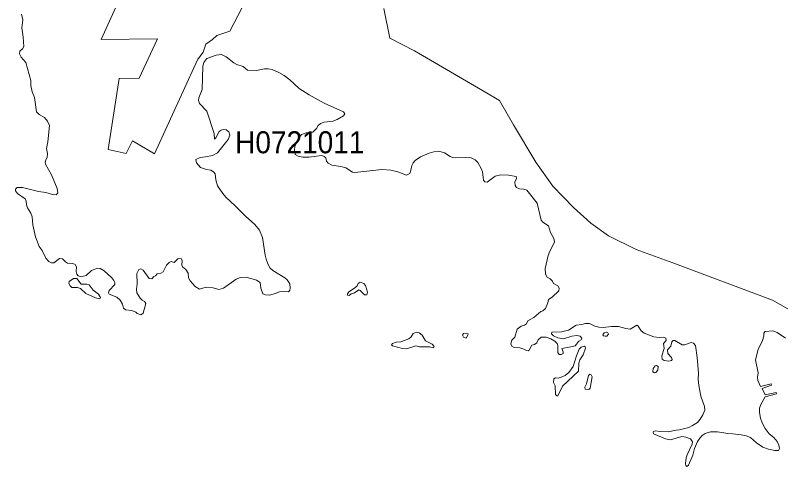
# Model space of a CAD drawing. Extents: x 369010 to 739155, y 6377141 to 6616555.
# Drawn here: x 385920 to 389405, y 6449209 to 6451258 of the extents above; entities that cross this region are included whole.
import ezdxf
from ezdxf.enums import TextEntityAlignment as Align

# ---------------------------------------------------------------- set-up
doc = ezdxf.new("R2010")
doc.units = 0
doc.header["$LTSCALE"] = 40
doc.layers.add('1', color=7, linetype='Continuous', lineweight=13)
doc.layers.add('2', color=7, linetype='Continuous')

msp = doc.modelspace()

# ---------------------------------------------------------------- linework, layer by layer
at = {"layer": '1'}
for points in [[(386471.87, 6451509.71), (386308.85, 6451148.91), (386564.22, 6451151.07), (386481.14, 6450972.32), (386390.94, 6450971.66), (386341.12, 6450648.93), (386421.56, 6450630.22), (386451.68, 6450687.82), (386550.65, 6450628.9), (386745.78, 6451055.74), (386747.27, 6451058.88), (386749.92, 6451061.86), (386772.26, 6451090.16), (386783.02, 6451126.9), (386813.31, 6451148.58), (386832.84, 6451165.8), (386891.92, 6451185.82), (387036.07, 6451462.54)], [(387036.07, 6451462.54), (386891.92, 6451185.82), (386832.84, 6451165.8), (386813.31, 6451148.58), (386783.02, 6451126.9), (386772.26, 6451090.16), (386749.92, 6451061.86), (386747.27, 6451058.88), (386745.78, 6451055.74), (386550.65, 6450628.9), (386451.68, 6450687.82), (386421.56, 6450630.22), (386341.12, 6450648.93), (386390.94, 6450971.66), (386481.14, 6450972.32), (386564.22, 6451151.07), (386308.85, 6451148.91), (386471.87, 6451509.71)], [(385948.05, 6451262.62), (385954.01, 6451237.96), (385948.88, 6451200.55), (385955.33, 6451158.68), (385958.64, 6451116.14), (385951.53, 6451106.05), (385939.28, 6451094.96), (385938.29, 6451083.21), (385946.07, 6451067.49), (385966.59, 6451044.32), (385989.92, 6450961.89), (385990.25, 6450939.72), (385995.05, 6450910.59), (386005.65, 6450885.27), (386014.75, 6450820.06), (386027.16, 6450808.47), (386051.99, 6450793.91), (386065.56, 6450777.03), (386073.83, 6450757.99), (386066.22, 6450684.34), (386060.1, 6450653.73), (386065.39, 6450631.55), (386064.57, 6450612.85), (386057.95, 6450601.59), (386055.46, 6450591.33), (386055.79, 6450581.73), (386083.27, 6450534.73), (386109.09, 6450472.66), (386112.89, 6450451.98), (386104.78, 6450443.21), (386088.4, 6450444.36), (386058.28, 6450454.46), (386024.18, 6450458.27), (385952.02, 6450476.47), (385928.36, 6450475.81), (385920.08, 6450469.35), (385919.58, 6450461.74), (385929.02, 6450449), (385964.27, 6450425.33), (385968.24, 6450414.41), (385969.73, 6450398.52), (385974.04, 6450383.62), (385989.59, 6450359.96), (385995.72, 6450342.74), (385999.36, 6450307.16), (386011.6, 6450252.88), (386027.66, 6450209.18), (386040.73, 6450190.31), (386057.61, 6450155.39), (386070.86, 6450140.5), (386083.1, 6450134.54)], [(387591.67, 6451288.6), (387617.99, 6451153.71), (387730.36, 6451097.28), (388021.15, 6450927.64), (388116.15, 6450871.86), (388179.54, 6450760.31), (388280.17, 6450591.66), (388357.79, 6450482.93), (388451.63, 6450385.11), (388529.58, 6450314.44), (388610.18, 6450257.34), (388735.8, 6450195.45), (388901.97, 6450134.87), (389354.12, 6449965.06), (389424.3, 6449925.67)], [(389424.3, 6449925.67), (389354.12, 6449965.06), (388901.97, 6450134.87), (388735.8, 6450195.45), (388610.18, 6450257.34), (388529.58, 6450314.44), (388451.63, 6450385.11), (388357.79, 6450482.93), (388280.17, 6450591.66), (388179.54, 6450760.31), (388116.15, 6450871.86), (388021.15, 6450927.64), (387730.36, 6451097.28), (387617.99, 6451153.71), (387591.67, 6451288.6)], [(387005.79, 6450308.65), (386963.09, 6450346.55), (386917.41, 6450393.88), (386875.04, 6450432.28), (386860.97, 6450448.67), (386836.64, 6450484.75), (386829.03, 6450510.73), (386825.55, 6450539.03), (386818.77, 6450548.3), (386806.52, 6450554.42), (386786.33, 6450557.73), (386759.19, 6450567.83), (386741.15, 6450588.02), (386738.66, 6450603.25), (386758.03, 6450613.01), (386782.85, 6450615), (386813.64, 6450621.12), (386836.15, 6450633.2), (386884.8, 6450693.94), (386892.25, 6450714.63), (386888.61, 6450728.7), (386875.7, 6450738.46), (386863.12, 6450739.29), (386853.36, 6450736.31), (386843.43, 6450730.02), (386828.86, 6450701.72), (386822.57, 6450695.27), (386820.92, 6450722.24), (386788.32, 6450822.87), (386755.05, 6450857.13), (386750.08, 6450871.69), (386751.24, 6450884.11), (386766.97, 6450921.68), (386770.77, 6451027.27), (386774.58, 6451043.98), (386788.81, 6451062.19), (386829.86, 6451077.91), (386855.01, 6451080.4), (386875.37, 6451070.3), (386911.28, 6451042), (386923.86, 6451035.05), (386952.33, 6451025.94), (386972.52, 6451009.06), (387013.57, 6451008.24), (387049.65, 6451014.52), (387066.69, 6451014.52), (387085.23, 6451011.38), (387114.36, 6450998.8), (387139.35, 6450984.4), (387164.67, 6450965.37), (387207.37, 6450926.15), (387251.73, 6450897.84), (387320.91, 6450858.79), (387407.96, 6450819.89), (387414.25, 6450811.45), (387407.8, 6450802.02), (387379.99, 6450785.63), (387360.13, 6450777.52), (387320.74, 6450772.56), (387304.03, 6450767.43), (387293.1, 6450758.32), (387286.15, 6450744.59), (387269.44, 6450728.2), (387254.54, 6450724.07), (387238.15, 6450724.4), (387218.13, 6450717.28), (387202.74, 6450697.75), (387187.84, 6450661.84), (387186.19, 6450647.11), (387188.67, 6450625.76), (387203.07, 6450617.98), (387224.09, 6450614.34), (387250.9, 6450614.34), (387309.82, 6450622.28), (387320.74, 6450616.82), (387327.69, 6450610.86), (387331, 6450596.13), (387338.95, 6450587.52), (387355.5, 6450578.26), (387395.55, 6450572.46), (387418.72, 6450565.18), (387449.67, 6450546.81), (387460.26, 6450544.16), (387582.24, 6450558.56), (387622.95, 6450554.75), (387654.4, 6450547.64), (387693.95, 6450532.74), (387708.68, 6450540.69), (387714.31, 6450554.59), (387717.62, 6450576.77), (387724.24, 6450588.52), (387733.67, 6450598.61), (387757.67, 6450615), (387796.73, 6450632.05), (387818.25, 6450638.83), (387841.09, 6450641.64), (387865.75, 6450634.03), (387891.9, 6450617.15), (387903.15, 6450612.02), (387916.39, 6450610.53)], [(387916.39, 6450610.53), (387961.08, 6450613.34), (387987.56, 6450610.53), (388004.93, 6450602.09), (388017.68, 6450589.84), (388034.23, 6450559.72), (388038.7, 6450547.47), (388042.67, 6450509.08), (388049.29, 6450502.79), (388060.71, 6450499.97), (388096.62, 6450528.61), (388122.44, 6450533.57), (388156.54, 6450532.74), (388191.62, 6450526.78), (388193.61, 6450517.19), (388186.16, 6450500.8), (388187.32, 6450485.57), (388192.45, 6450476.64), (388206.35, 6450470.35), (388224.56, 6450469.52), (388239.79, 6450463.89), (388286.29, 6450405.64), (388305.66, 6450328.51), (388311.94, 6450318.42), (388337.76, 6450303.02), (388347.36, 6450272.74), (388362.92, 6450245.43), (388365.24, 6450229.37), (388352.82, 6450203.89), (388344.55, 6450187.34), (388337.27, 6450168.47), (388323.36, 6450108.89), (388325.02, 6450082.41), (388332.3, 6450069.66), (388345.71, 6450061.55), (388356.63, 6450050.8), (388361.27, 6450040.53), (388380.46, 6450029.94), (388387.25, 6450019.02), (388385.1, 6450007.6), (388355.47, 6449978.47), (388338.92, 6449968.04), (388335.12, 6449952.65), (388324.69, 6449926.67), (388312.77, 6449916.41), (388303.5, 6449914.25), (388271.73, 6449886.78), (388244.09, 6449871.22), (388238.13, 6449857.32), (388230.02, 6449851.86), (388214.79, 6449847.56), (388196.59, 6449832.83), (388186, 6449796.91), (388172.59, 6449783.34), (388166.8, 6449766.62), (388171.27, 6449756.53), (388182.85, 6449750.57), (388207.68, 6449748.75), (388226.21, 6449742.79), (388238.13, 6449735.84), (388245.58, 6449734.35), (388250.21, 6449737.83), (388262.62, 6449760.5), (388274.87, 6449763.98), (388285.46, 6449771.92), (388291.26, 6449785.16), (388304.33, 6449797.24), (388327.67, 6449797.24), (388348.36, 6449789.63), (388366.4, 6449779.7), (388376.99, 6449769.11), (388381.29, 6449758.85), (388380.3, 6449728.06), (388386.59, 6449718.79), (388396.35, 6449718.96), (388404.46, 6449723.59), (388404.46, 6449730.54), (388399, 6449745.44), (388439.88, 6449752.56), (388459.24, 6449758.02), (388476.29, 6449778.71), (388486.55, 6449785), (388490.03, 6449792.28), (388482.41, 6449802.37), (388467.52, 6449804.86), (388444.02, 6449802.04), (388405.95, 6449790.29), (388380.46, 6449794.43), (388360.77, 6449802.54), (388351.5, 6449812.63), (388353.98, 6449819.42), (388397.51, 6449821.74), (388429.62, 6449828.52), (388463.22, 6449851.86), (388489.03, 6449854.84), (388506.74, 6449858.98), (388524.62, 6449859.31), (388548.62, 6449846.73), (388567.15, 6449842.09), (388587.01, 6449840.94)], [(386083.1, 6450134.54), (386094.85, 6450134.21), (386119.68, 6450154.07), (386134.08, 6450152.75), (386146.82, 6450139.67), (386156.59, 6450133.22), (386180.09, 6450131.56), (386191.18, 6450126.93), (386196.97, 6450116), (386195.65, 6450095.81), (386197.96, 6450083.07), (386204.25, 6450075.95), (386213.19, 6450072.48), (386229.24, 6450073.3), (386240.83, 6450077.61), (386265.49, 6450099.45), (386291.64, 6450111.04), (386304.38, 6450108.89), (386321.92, 6450097.8), (386356.85, 6450066.19), (386366.61, 6450053.94), (386370.75, 6450045), (386370.42, 6450035.73), (386345.59, 6450008.43), (386341.62, 6449998.33), (386344.6, 6449992.37), (386380.51, 6449978.47), (386394.58, 6449965.73), (386405.01, 6449946.36), (386410.47, 6449928.49), (386419.74, 6449921.7), (386447.71, 6449917.73), (386466.74, 6449909.95), (386472.53, 6449903.99), (386488.26, 6449899.03), (386500.01, 6449905.81), (386510.93, 6449949.18), (386505.97, 6449959.27), (386494.88, 6449965.23), (386486.1, 6449974.5), (386471.37, 6449998.16), (386468.89, 6450015.21), (386472.04, 6450039.54), (386471.21, 6450086.38), (386480.15, 6450103.76), (386489.41, 6450107.23), (386499.68, 6450101.6), (386526.98, 6450063.21), (386538.57, 6450062.38), (386547.67, 6450072.97), (386555.78, 6450074.79), (386563.06, 6450085.22), (386578.95, 6450087.04), (386590.04, 6450093.33), (386605.27, 6450124.11), (386617.35, 6450136.36), (386626.78, 6450140.17), (386639.86, 6450136.69), (386655.91, 6450153.24), (386665.18, 6450156.22), (386673.29, 6450152.25), (386676.43, 6450143.81), (386674.45, 6450124.44), (386677.76, 6450116.17), (386693.32, 6450104.25), (386703.25, 6450087.7), (386704.9, 6450066.68), (386712.02, 6450053.28), (386736.02, 6450027.46), (386755.38, 6450015.05), (386785.01, 6450023.65), (386816.78, 6450020.34), (386843.26, 6450012.73), (386863.95, 6450020.18), (386920.55, 6450060.39), (386940.74, 6450067.84), (386967.39, 6450069.66), (387013.9, 6450056.59), (387030.28, 6450045.66), (387033.76, 6450020.18), (387041.7, 6449994.19), (387053.62, 6449988.57), (387073.48, 6449988.23), (387098.3, 6449995.02), (387117.34, 6450002.96), (387136.04, 6450004.95), (387158.71, 6450003.3), (387165.17, 6450010.91), (387166.82, 6450020.18), (387165, 6450038.71), (387152.09, 6450057.08), (387141.83, 6450067.18), (387087.05, 6450099.29), (387076.29, 6450110.21), (387064.21, 6450129.24), (387057.09, 6450150.59), (387052.96, 6450169.3), (387041.04, 6450249.57), (387026.48, 6450282.34), (387005.79, 6450308.65)], [(388587.01, 6449840.94), (388623.42, 6449845.4), (388656.19, 6449845.9), (388689.79, 6449836.96), (388708.66, 6449833.98), (388738.61, 6449851.36), (388745.07, 6449847.56), (388758.47, 6449825.21), (388772.54, 6449815.94), (388816.73, 6449798.24), (388841.56, 6449795.59), (388860.26, 6449797.08), (388871.18, 6449791.95), (388872.51, 6449782.51), (388859.43, 6449769.11), (388862.91, 6449745.94), (388851.82, 6449712.5), (388853.31, 6449696.78), (388862.58, 6449691.82), (388884.26, 6449688.84), (388895.84, 6449691.82), (388898.99, 6449696.12), (388896.67, 6449705.22), (388880.29, 6449723.1), (388878.13, 6449740.31), (388893.53, 6449756.03), (388897.99, 6449776.55), (388904.28, 6449781.85), (388911.9, 6449782.51), (388944, 6449762.65), (388955.09, 6449762.32), (388985.88, 6449772.42), (388995.64, 6449770.43), (389004.58, 6449759.84), (389013.35, 6449704.89), (389018.81, 6449634.39), (389017.16, 6449604.76), (389019.81, 6449577.78), (389030.07, 6449528.8), (389046.62, 6449482.12), (389047.28, 6449466.07), (389038.84, 6449444.55), (389027.09, 6449424.53), (389013.68, 6449410.29), (388991.17, 6449395.4), (388974.79, 6449387.79), (388932.92, 6449376.04), (388918.19, 6449374.88), (388881.78, 6449367.93), (388845.03, 6449368.42), (388822.86, 6449371.4), (388813.75, 6449367.93), (388814.91, 6449358.82), (388868.53, 6449335.82), (388891.87, 6449331.68), (388943.34, 6449346.08), (388961.88, 6449342.77), (388982.57, 6449335.16), (388991.5, 6449322.41), (388990.68, 6449311.82), (388967.67, 6449263), (388962.87, 6449249.76), (388959.07, 6449223.61), (388962.04, 6449213.84), (388966.18, 6449209.37), (388973.8, 6449216.49), (388993.32, 6449262.17), (389000.11, 6449291.13), (389014.51, 6449323.41), (389024.61, 6449338.96), (389034.7, 6449350.71), (389048.77, 6449360.48), (389072.6, 6449367.76), (389105.54, 6449367.1), (389151.22, 6449359.15), (389174.06, 6449358.33), (389211.96, 6449353.69), (389235.62, 6449348.73), (389254.66, 6449341.11), (389282.63, 6449316.95), (389309.93, 6449298.41), (389335.75, 6449289.15), (389364.88, 6449282.86), (389382.26, 6449283.19), (389385.73, 6449291.3), (389383.58, 6449307.35), (389375.8, 6449323.41), (389359.92, 6449341.94), (389340.06, 6449358.66), (389321.02, 6449382.49), (389307.78, 6449407.81), (389300, 6449429.82), (389295.2, 6449455.15), (389295.2, 6449474.84), (389301.49, 6449491.72), (389321.35, 6449525.98), (389372.83, 6449540.38), (389371.17, 6449546.17), (389321.35, 6449534.75), (389307.95, 6449564.38)], [(389307.95, 6449564.38), (389350.48, 6449579.44), (389348.5, 6449585.4), (389300.33, 6449573.15), (389288.58, 6449601.12), (389287.09, 6449615.35), (389289.25, 6449635.38), (389277.16, 6449693.64), (389289.74, 6449741.8), (389309.11, 6449782.18), (389315.89, 6449801.71), (389314.73, 6449815.61), (389320.69, 6449823.56), (389356.44, 6449825.71), (389375.47, 6449818.1), (389413.04, 6449793.27)]]:
    msp.add_lwpolyline(points, dxfattribs=at)
for points in [[(386303.39, 6449971.68), (386305.21, 6449976.65), (386296.77, 6449992.37), (386272.27, 6450009.75), (386253.74, 6450034.08), (386243.31, 6450037.89), (386218.82, 6450037.55), (386198.96, 6450063.21), (386184.06, 6450063.21), (386164.2, 6450049.31), (386162.54, 6450041.2), (386167.68, 6450029.78), (386176.12, 6450021.83), (386200.94, 6450023.16), (386215.17, 6450018.03), (386239.17, 6449995.19), (386283.53, 6449974.99)], [(387503.46, 6449988.9), (387513.72, 6449989.56), (387517.03, 6450000.81), (387508.59, 6450031.1), (387499.98, 6450041.03), (387483.27, 6450046.16), (387474.66, 6450040.04), (387469.7, 6450029.78), (387458.44, 6450019.02), (387432.95, 6450002.96), (387426.17, 6449994.19), (387426.17, 6449988.4), (387433.28, 6449986.58), (387443.21, 6449993.86), (387458.44, 6449998.99), (387477.47, 6450012.4), (387484.59, 6450008.92)], [(387797.89, 6449752.72), (387817.09, 6449749.08), (387820.07, 6449755.37), (387811.13, 6449765.63), (387780.84, 6449780.03), (387765.78, 6449805.68), (387751.71, 6449816.28), (387738.8, 6449819.42), (387724.24, 6449813.3), (387715.63, 6449798.07), (387704.21, 6449789.96), (387668.13, 6449775.56), (387647.12, 6449774.57), (387630.07, 6449768.78), (387626.59, 6449762.82), (387631.23, 6449757.52), (387676.58, 6449745.94), (387694.28, 6449744.61), (387736.82, 6449757.69), (387753.04, 6449753.55)], [(387964.06, 6449792.61), (387972.83, 6449805.52), (387973.32, 6449811.81), (387966.87, 6449815.78), (387951.97, 6449813.13), (387948.17, 6449805.85), (387953.3, 6449796.91)], [(388601.08, 6449819.42), (388591.32, 6449817.1), (388585.03, 6449808.33), (388588.01, 6449803.2), (388595.12, 6449801.05), (388603.07, 6449802.37), (388610.35, 6449809.99), (388607.37, 6449817.1)], [(388499.79, 6449756.03), (388486.88, 6449751.4), (388477.78, 6449741.96), (388465.2, 6449712.5), (388450.14, 6449663.52), (388430.94, 6449637.04), (388414.56, 6449623.79), (388395.69, 6449615.02), (388381.95, 6449610.72), (388369.87, 6449612.54), (388362.26, 6449608.57), (388361.43, 6449591.02), (388369.04, 6449576.46), (388369.87, 6449537.4), (388375.33, 6449530.95), (388381.13, 6449530.95), (388402.14, 6449574.81), (388474.97, 6449643.32), (388475.46, 6449678.74), (388480.1, 6449693.47), (388495.32, 6449717.47), (388506.08, 6449747.59), (388504.43, 6449753.38)], [(388827.66, 6449668.65), (388821.7, 6449667.32), (388813.09, 6449655.57), (388811.6, 6449639.52), (388818.55, 6449635.71), (388825.83, 6449636.04), (388834.61, 6449647.46), (388835.93, 6449663.85)], [(388526.27, 6449628.93), (388519.16, 6449623.79), (388511.05, 6449584.57), (388503.1, 6449570.67), (388505.09, 6449561.73), (388521.31, 6449559.25), (388527.43, 6449565.54), (388536.7, 6449616.68), (388532.23, 6449625.62)]]:
    msp.add_lwpolyline(points, close=True, dxfattribs=at)

# ---------------------------------------------------------------- texts
at = {"layer": '2', "width": 0.95}
msp.add_text('H0721011', height=100, dxfattribs=at).set_placement((387209.89, 6450631.74), align=Align.CENTER)

doc.saveas('drawing.dxf')
